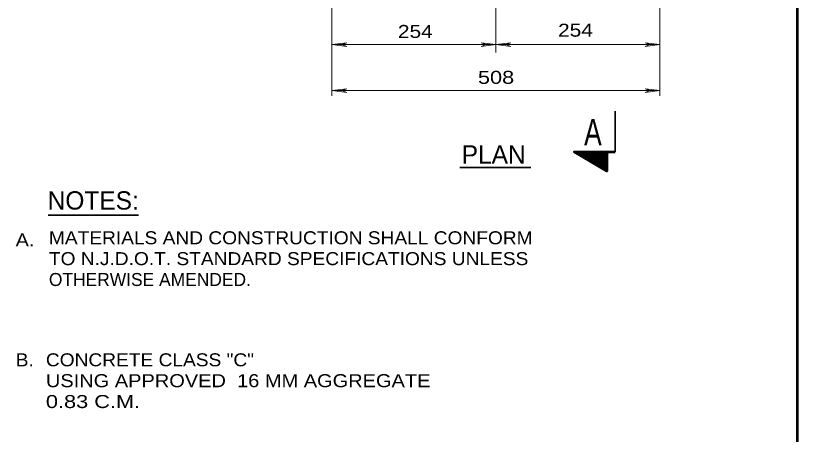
# Model space of a CAD drawing. Extents: x 312583 to 312854, y 144419 to 144597.
# Drawn here: x 312621.24 to 312666.92, y 144489.11 to 144513.6 of the extents above; entities that cross this region are included whole.
import ezdxf
from ezdxf.enums import TextEntityAlignment as Align

# ---------------------------------------------------------------- set-up
doc = ezdxf.new("R2010")
doc.units = 0
doc.header["$LTSCALE"] = 0.3
doc.layers.add('1', color=7, linetype='Continuous', lineweight=13)

msp = doc.modelspace()

# ---------------------------------------------------------------- linework, layer by layer
at = {"layer": '1', "lineweight": 53}
for p, q in [((312666.9226, 144486.1644), (312666.9226, 144523.38)), ((312655.7927, 144505.6279), (312656.268, 144505.6279))]:
    msp.add_line(p, q, dxfattribs=at)
at = {"layer": '1'}
for p, q in [((312649.3067, 144519.9645), (312649.3067, 144511.4545)), ((312639.7234, 144516.3842), (312639.7234, 144508.9092)), ((312658.89, 144516.3842), (312658.89, 144508.9092)), ((312639.7234, 144511.9069), (312640.5897, 144512.0142)), ((312639.7234, 144511.9069), (312640.5897, 144511.7995)), ((312640.5897, 144512.0142), (312640.3137, 144511.9069)), ((312640.5897, 144511.7995), (312640.3137, 144511.9069)), ((312648.4404, 144512.0142), (312648.7164, 144511.9069)), ((312649.3067, 144511.9069), (312648.4404, 144512.0142)), ((312648.4404, 144511.7995), (312648.7164, 144511.9069)), ((312649.3067, 144511.9069), (312648.4404, 144511.7995)), ((312649.3067, 144511.9069), (312650.173, 144512.0142)), ((312649.3067, 144511.9069), (312650.173, 144511.7995)), ((312650.173, 144512.0142), (312649.897, 144511.9069)), ((312650.173, 144511.7995), (312649.897, 144511.9069)), ((312658.0237, 144512.0142), (312658.2997, 144511.9069)), ((312658.89, 144511.9069), (312658.0237, 144512.0142)), ((312658.0237, 144511.7995), (312658.2997, 144511.9069)), ((312658.89, 144511.9069), (312658.0237, 144511.7995)), ((312639.7234, 144509.2235), (312640.5897, 144509.3309)), ((312639.7234, 144509.2235), (312658.89, 144509.2235)), ((312639.7234, 144509.2235), (312640.5897, 144509.1162)), ((312640.5897, 144509.3309), (312640.3137, 144509.2235)), ((312640.5897, 144509.1162), (312640.3137, 144509.2235)), ((312658.0237, 144509.3309), (312658.2997, 144509.2235)), ((312658.89, 144509.2235), (312658.0237, 144509.3309)), ((312658.0237, 144509.1162), (312658.2997, 144509.2235)), ((312658.89, 144509.2235), (312658.0237, 144509.1162))]:
    msp.add_line(p, q, dxfattribs=at)
at = {"layer": '1', "lineweight": 35}
for p, q in [((312656.268, 144508.0199), (312656.268, 144505.6279)), ((312653.8914, 144505.6279), (312653.8914, 144505.6125)), ((312653.922, 144505.6279), (312653.9144, 144505.6049)), ((312653.9527, 144505.6279), (312653.9297, 144505.5895)), ((312653.9757, 144505.6279), (312653.9527, 144505.5819)), ((312654.0064, 144505.6279), (312653.9757, 144505.5665)), ((312654.0294, 144505.6279), (312653.991, 144505.5589)), ((312654.06, 144505.6279), (312654.014, 144505.5435)), ((312654.0907, 144505.6279), (312654.037, 144505.5359)), ((312654.1214, 144505.6279), (312654.0524, 144505.5205)), ((312654.1444, 144505.6279), (312654.0754, 144505.5129)), ((312654.1674, 144505.6279), (312654.0984, 144505.4975)), ((312654.198, 144505.6279), (312654.1214, 144505.4899)), ((312654.221, 144505.6279), (312654.1367, 144505.4745)), ((312654.2517, 144505.6279), (312654.1597, 144505.4592)), ((312654.2824, 144505.6279), (312654.1827, 144505.4515)), ((312654.313, 144505.6279), (312654.198, 144505.4362)), ((312654.336, 144505.6279), (312654.221, 144505.4209)), ((312654.3667, 144505.6279), (312654.244, 144505.4132)), ((312654.3897, 144505.6279), (312654.2594, 144505.3979)), ((312654.4204, 144505.6279), (312654.2824, 144505.3902)), ((312654.451, 144505.6279), (312654.3054, 144505.3749)), ((312654.474, 144505.6279), (312654.3207, 144505.3672)), ((312654.5047, 144505.6279), (312654.3514, 144505.3519)), ((312654.5277, 144505.6279), (312654.3667, 144505.3442)), ((312654.5584, 144505.6279), (312654.3897, 144505.3289)), ((312654.589, 144505.6279), (312654.4127, 144505.3212)), ((312654.612, 144505.6279), (312654.428, 144505.3059)), ((312654.6427, 144505.6279), (312654.451, 144505.2982)), ((312654.6657, 144505.6279), (312654.474, 144505.2829)), ((312654.6964, 144505.6279), (312654.4894, 144505.2675)), ((312654.7194, 144505.6279), (312654.5124, 144505.2599)), ((312654.75, 144505.6279), (312654.5354, 144505.2445)), ((312654.7807, 144505.6279), (312654.5507, 144505.2292)), ((312654.8114, 144505.6279), (312654.5737, 144505.2215)), ((312654.8344, 144505.6279), (312654.5967, 144505.2062)), ((312654.8574, 144505.6279), (312654.6197, 144505.1985)), ((312654.888, 144505.6279), (312654.635, 144505.1832)), ((312654.9187, 144505.6279), (312654.658, 144505.1755)), ((312654.9417, 144505.6279), (312654.681, 144505.1602)), ((312654.9724, 144505.6279), (312654.6964, 144505.1525)), ((312655.003, 144505.6279), (312654.7194, 144505.1372)), ((312655.026, 144505.6279), (312654.7424, 144505.1295)), ((312655.0567, 144505.6279), (312654.7577, 144505.1142)), ((312655.0874, 144505.6279), (312654.7807, 144505.1065)), ((312655.1104, 144505.6279), (312654.8037, 144505.0912)), ((312655.141, 144505.6202), (312654.819, 144505.0759)), ((312655.164, 144505.6279), (312654.8497, 144505.0682)), ((312655.1947, 144505.6279), (312654.865, 144505.0529)), ((312655.2177, 144505.6279), (312654.888, 144505.0452)), ((312655.2484, 144505.6279), (312654.911, 144505.0299)), ((312655.279, 144505.6279), (312654.9264, 144505.0222)), ((312655.3097, 144505.6279), (312654.9494, 144505.0069)), ((312655.3327, 144505.6279), (312654.9724, 144504.9992)), ((312655.3557, 144505.6279), (312654.9877, 144504.9839)), ((312655.3864, 144505.6202), (312655.0107, 144504.9762)), ((312655.417, 144505.6279), (312655.0337, 144504.9609)), ((312655.44, 144505.6279), (312655.049, 144504.9532)), ((312655.4707, 144505.6279), (312655.072, 144504.9379)), ((312655.5014, 144505.6279), (312655.095, 144504.9225)), ((312655.5244, 144505.6279), (312655.118, 144504.9149)), ((312655.555, 144505.6279), (312655.1334, 144504.8995)), ((312655.5857, 144505.6279), (312655.1564, 144504.8842)), ((312655.6087, 144505.6202), (312655.1794, 144504.8765)), ((312655.6394, 144505.6202), (312655.1947, 144504.8612)), ((312655.6624, 144505.6279), (312655.2177, 144504.8535)), ((312655.693, 144505.6279), (312655.2407, 144504.8382)), ((312655.716, 144505.6279), (312655.256, 144504.8305)), ((312655.7467, 144505.6279), (312655.279, 144504.8152)), ((312655.7774, 144505.6279), (312655.302, 144504.8075)), ((312655.7927, 144505.6049), (312655.3174, 144504.7922)), ((312655.7927, 144505.5512), (312655.348, 144504.7845)), ((312655.7927, 144505.5129), (312655.3634, 144504.7692)), ((312655.7927, 144505.4592), (312655.3864, 144504.7615)), ((312655.7927, 144505.4132), (312655.4094, 144504.7462)), ((312655.7927, 144505.3672), (312655.4247, 144504.7309)), ((312655.7927, 144505.3212), (312655.4477, 144504.7232)), ((312655.7927, 144505.2675), (312655.4707, 144504.7079)), ((312655.7927, 144505.2215), (312655.486, 144504.6925)), ((312655.7927, 144505.1755), (312655.509, 144504.6849)), ((312655.7927, 144505.1219), (312655.5244, 144504.6695)), ((312655.7927, 144505.0759), (312655.5474, 144504.6619)), ((312655.7927, 144505.0299), (312655.5704, 144504.6465)), ((312655.7927, 144504.9762), (312655.5857, 144504.6389)), ((312655.7927, 144504.9302), (312655.6164, 144504.6235)), ((312655.7927, 144504.8842), (312655.6317, 144504.6159)), ((312655.7927, 144504.8382), (312655.6547, 144504.6005)), ((312647.1941, 144504.7243), (312651.3477, 144504.7243)), ((312655.7927, 144504.7845), (312655.6777, 144504.5929)), ((312655.7927, 144504.7462), (312655.693, 144504.5775)), ((312655.7927, 144504.6925), (312655.716, 144504.5699)), ((312655.7927, 144504.6465), (312655.739, 144504.5545)), ((312655.7927, 144504.5929), (312655.7544, 144504.5392)), ((312655.7927, 144504.5469), (312655.7774, 144504.5315)), ((312623.1433, 144501.926), (312628.4336, 144501.926))]:
    msp.add_line(p, q, dxfattribs=at)
at = {"layer": '1'}
msp.add_lwpolyline([(312639.7234, 144511.9069), (312649.3067, 144511.9069), (312658.89, 144511.9069)], dxfattribs=at)
at = {"layer": '1', "lineweight": 53}
msp.add_lwpolyline([(312655.7927, 144505.6279), (312655.7927, 144504.5162), (312653.876, 144505.6279)], close=True, dxfattribs=at)

# ---------------------------------------------------------------- texts
at = {"layer": '1'}
for s, width, p in [('254 ', 1.2, (312643.5828, 144512.2973)), ('254 ', 1.2, (312652.9395, 144512.3718)), ('508 ', 1.25, (312648.2563, 144509.6138)), ('A.   ', 1.15, (312621.2427, 144500.1032)), ('MATERIALS AND CONSTRUCTION SHALL CONFORM', 1.1, (312623.1893, 144500.2306)), ('TO N.J.D.O.T. STANDARD SPECIFICATIONS UNLESS', 1.1, (312623.1893, 144499.0106)), ('B.   ', 1.1, (312621.2512, 144493.093)), ('CONCRETE CLASS "C"', 1.1, (312623.013, 144493.093)), ('USING APPROVED  16 MM AGGREGATE', 1.15, (312623.013, 144491.873)), ('0.83 C.M.', 1.25, (312623.013, 144490.653))]:
    msp.add_text(s, height=0.76, dxfattribs=dict(at, width=width)).set_placement(p)
at = {"layer": '1', "width": 0.75}
msp.add_text('A', height=1.533, dxfattribs=at).set_placement((312654.9762, 144506.0265), align=Align.CENTER)
at = {"layer": '1'}
for s, p in [('PLAN', (312649.1784, 144504.9496)), ('NOTES:', (312625.7789, 144502.2597))]:
    msp.add_text(s, height=1.07, dxfattribs=at).set_placement(p, align=Align.CENTER)
msp.add_text('OTHERWISE AMENDED.', height=0.76, dxfattribs=at).set_placement((312623.1893, 144497.7906))

doc.saveas('drawing.dxf')
